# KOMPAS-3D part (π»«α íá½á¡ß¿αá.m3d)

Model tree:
1. Эскиз:1
2. Операция выдавливания:1
     Расстояние 1 = 1.5
3. Эскиз:2
4. Вырезать элемент выдавливания:1
     Расстояние 1 = 0.5
5. Эскиз:3
6. Операция выдавливания:2
     Расстояние 1 = 0.5
7. Эскиз:4
8. Операция выдавливания:3
     Расстояние 1 = 1
9. Эскиз:5
10. Вырезать элемент выдавливания:2
     Расстояние 1 = 5.31827; Угол 1 = 8
11. Скругление:1
     Радиус = 0.1

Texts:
  Сплав АЛ8  ГОСТ 1583-93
